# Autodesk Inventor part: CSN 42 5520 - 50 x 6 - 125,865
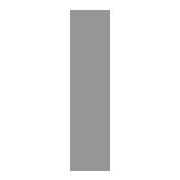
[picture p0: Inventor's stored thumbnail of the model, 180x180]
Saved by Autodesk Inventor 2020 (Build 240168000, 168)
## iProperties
Created: 2019-01
Part Number: CSN 42 5520 - 50 x 6 - 125,865
Material: Ocel
Description: Tyč
Document SubType Name: Modeling
Standard: CSN 42 5520
Designer: doma
Standards Organization: CSN
Language: cs-CZ
Size Designation: 50 x 6 - 125,865
Categories: <MemberInstance><Categories><Category DisplayName="Konstrukční profily" InternalName="089c4875-fa83-4c05-b084-43b9cc11f5ed" Mnemonic="GRDR"><CategoryParameter D
Stock Number: 50 x 6
Density: 7.85 g/cm^3
Appearance: Plech
Mass: 296.412 g
Surface Area: 146.969 cm^2
Volume: 37.7595 cm^3
IsCustomPart: 1
G_L: 125,865 mm
Author: doma
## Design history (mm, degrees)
node "Počáteční rovina"
node "Koncová rovina"
sketch "Náčrt"
  geometry: L1 (3, -25)-(-3, -25); L2 (-3, -25)-(-3, 25); L3 (-3, 25)-(3, 25); L4 (3, 25)-(3, -25); L5 (-6, 0)-(8, 0); L6 (0, -30)-(0, 40); L7 (0, 54)-(0, -44) reference; L8 (-9.2, 0)-(13.2, 0) reference
  constraints: 12 end point, 2 collinear, 2 parallel, 1 horizontal, 1 perpendicular
  dimensions: "d0" = 50 distance between parallel lines of L3 L1 (= G_W); "d1" = 6 distance between parallel lines of L4 L2 (= G_H); "d4" = 3 distance between parallel lines of L6 L4 (= 0.5 x d1); "d5" = 25 distance between parallel lines of L5 L3 (= 0.5 x d0)
extrude "Těleso" new body sketch "Náčrt" stored distance "d2" = 125.865 (= G_L); taper "d3" = 0 deg
node "Driven Length"
  sketch "Sketch3"
    geometry: L1 (0, 0)-(10, 0) reference
    constraints: 2 end point, 1 horizontal
  workplane "Work Plane3"
  sketch "Sketch4"
    geometry: L1 (-2, 0)-(12, 0) reference; L2 (-2, 125.865)-(12, 125.865) reference
    dimensions: "d9" = 125.865 distance between parallel lines of L1 L2 (derived)
body "Solid1"
other parameters: "G_W" = 50 [user parameter; used in 1 equation term], "G_H" = 6 [user parameter; used in 1 equation term], "G_L" = 125.865 (= d9) [user parameter; used in 1 equation term], "G_OFFSET_START" = 0 [user parameter; used in 1 equation term], "G_OFFSET_END" = 0 [user parameter; used in 1 equation term], "d6" = 0 (computed from G_OFFSET_START), "d7" = 125.865 (= G_OFFSET_END + B_L), "B_L" = 125.865 [user parameter; used in 1 equation term], "d8" = 90 deg
